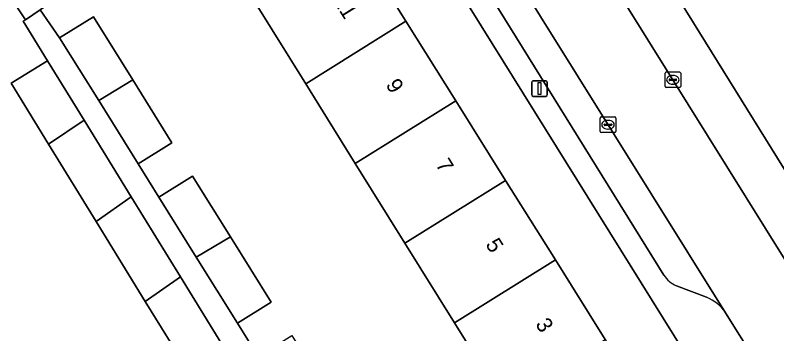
# Model space of a CAD drawing. Extents: x 160030 to 160839, y 385325 to 386450.
# Drawn here: x 160188.9 to 160237.55, y 386041.56 to 386061.92 of the extents above; entities that cross this region are included whole.
import ezdxf

# ---------------------------------------------------------------- set-up
doc = ezdxf.new("R2010")
doc.units = 0
for name, color, linetype in [('IMGEO_Erf', 7, 'Continuous'), ('IMGEO_Groenvoorziening', 7, 'Continuous'), ('IMGEO_Kolk', 7, 'Continuous'), ('IMGEO_Lichtmast', 7, 'Continuous'), ('IMGEO_Pand', 7, 'Continuous'), ('IMGEO_Pand_nummerreeks', 7, 'Continuous'), ('IMGEO_Parkeervlak_open', 7, 'Continuous'), ('IMGEO_Rijbaan_lokaal_open', 7, 'Continuous'), ('IMGEO_Voetpad_open', 7, 'Continuous')]:
    doc.layers.add(name, color=color, linetype=linetype)

msp = doc.modelspace()

# ---------------------------------------------------------------- linework, layer by layer
at = {"layer": 'IMGEO_Erf'}
for points in [[(160233.001, 386038.217), (160186.576, 386112.811)], [(160188.863, 386067.169), (160191.665, 386063.073), (160190.502, 386062.278), (160191.73, 386060.483), (160193.89, 386061.83), (160196.403, 386057.8), (160198.912, 386053.776), (160196.752, 386052.429), (160198.071, 386050.296), (160200.231, 386051.643), (160202.657, 386047.753), (160205.253, 386043.589), (160203.093, 386042.242), (160204.413, 386040.108), (160206.573, 386041.455), (160209.212, 386037.222), (160211.595, 386033.401), (160209.435, 386032.054), (160211.013, 386029.444), (160213.092, 386030.866), (160215.847, 386026.838), (160213.769, 386025.416), (160215.969, 386022.176), (160231.871, 386032.971)], [(160210.679, 386066.631), (160213.861, 386061.544), (160217.042, 386056.457), (160220.223, 386051.37), (160223.405, 386046.283), (160226.586, 386041.195), (160229.809, 386036.042), (160223.345, 386032.012), (160220.139, 386037.163), (160216.968, 386042.257), (160213.797, 386047.352), (160210.626, 386052.445), (160207.456, 386057.539), (160204.285, 386062.632)], [(160197.208, 386043.633), (160194.065, 386048.741), (160191.02, 386053.691), (160188.632, 386057.573), (160190.967, 386059.01), (160189.915, 386060.72), (160189.415, 386061.534), (160189.561, 386061.634), (160188.783, 386062.773)], [(160197.547, 386009.869), (160197.929, 386010.149), (160205.189, 386014.858), (160214.711, 386021.322), (160212.505, 386024.571), (160210.408, 386023.137), (160207.666, 386027.146), (160209.763, 386028.58), (160208.335, 386030.651), (160206.23, 386029.324), (160203.626, 386033.454), (160201.272, 386037.189), (160203.378, 386038.516), (160202.274, 386040.629), (160199.939, 386039.193), (160197.208, 386043.633)]]:
    msp.add_lwpolyline(points, dxfattribs=at)
at = {"layer": 'IMGEO_Groenvoorziening'}
msp.add_lwpolyline([(160212.738, 386092.855), (160243.449, 386043.345)], dxfattribs=at)
at = {"layer": 'IMGEO_Kolk'}
for p, q in [((160230.411, 386057.369), (160230.411, 386058.221)), ((160230.486, 386058.295), (160231.338, 386058.295)), ((160230.899, 386058.075), (160230.924, 386058.075)), ((160231.412, 386058.221), (160231.412, 386057.369)), ((160230.67, 386057.789), (160230.67, 386057.801)), ((160231.108, 386057.752), (160230.71, 386057.752)), ((160230.713, 386057.838), (160231.111, 386057.838)), ((160230.922, 386057.515), (160230.897, 386057.515)), ((160231.154, 386057.801), (160231.154, 386057.789)), ((160231.338, 386057.295), (160230.486, 386057.295)), ((160226.27, 386054.5), (160226.27, 386055.352)), ((160226.345, 386055.426), (160227.197, 386055.426)), ((160226.758, 386055.206), (160226.783, 386055.206)), ((160227.271, 386055.352), (160227.271, 386054.5)), ((160226.529, 386054.92), (160226.529, 386054.932)), ((160226.967, 386054.883), (160226.569, 386054.883)), ((160226.572, 386054.969), (160226.97, 386054.969)), ((160226.781, 386054.646), (160226.756, 386054.646)), ((160227.013, 386054.932), (160227.013, 386054.92)), ((160227.197, 386054.426), (160226.345, 386054.426))]:
    msp.add_line(p, q, dxfattribs=at)
for points in [[(160230.411, 386057.369), (160230.411, 386058.221)], [(160230.486, 386058.295), (160231.338, 386058.295)], [(160231.412, 386058.221), (160231.412, 386057.369)], [(160231.338, 386057.295), (160230.486, 386057.295)], [(160226.27, 386054.5), (160226.27, 386055.352)], [(160226.345, 386055.426), (160227.197, 386055.426)], [(160227.271, 386055.352), (160227.271, 386054.5)], [(160227.197, 386054.426), (160226.345, 386054.426)]]:
    msp.add_lwpolyline(points, dxfattribs=at)
for centre, radius, start, end in [((160230.488, 386058.219), 0.0765, 91.552, 178.448), ((160230.488, 386058.219), 0.0765, 91.552, 178.448), ((160231.336, 386058.219), 0.0765, 1.552, 88.448), ((160231.336, 386058.219), 0.0765, 1.552, 88.448), ((160230.71, 386057.798), 0.0403, 85.8775, 175.7526), ((160230.707, 386057.788), 0.0366, 178.938, 274.7102), ((160231.111, 386057.795), 0.043, 264.8664, 352.4533), ((160231.115, 386057.8), 0.0386, 1.7309, 96.639), ((160230.488, 386057.371), 0.0765, 181.552, 268.448), ((160230.488, 386057.371), 0.0765, 181.552, 268.448), ((160231.336, 386057.371), 0.0765, 271.552, 358.448), ((160231.336, 386057.371), 0.0765, 271.552, 358.448), ((160226.347, 386055.35), 0.0765, 91.552, 178.448), ((160226.347, 386055.35), 0.0765, 91.552, 178.448), ((160227.195, 386055.35), 0.0765, 1.552, 88.448), ((160227.195, 386055.35), 0.0765, 1.552, 88.448), ((160226.569, 386054.929), 0.0403, 85.8775, 175.7526), ((160226.566, 386054.919), 0.0366, 178.938, 274.7102), ((160226.97, 386054.926), 0.043, 264.8664, 352.4533), ((160226.974, 386054.931), 0.0386, 1.7309, 96.639), ((160226.347, 386054.502), 0.0765, 181.552, 268.448), ((160226.347, 386054.502), 0.0765, 181.552, 268.448), ((160227.195, 386054.502), 0.0765, 271.552, 358.448), ((160227.195, 386054.502), 0.0765, 271.552, 358.448)]:
    msp.add_arc(centre, radius, start, end, dxfattribs=at)
for centre, major_axis, ratio, start_param, end_param in [((160230.898, 386057.795), (-0.387, 0.002), 0.722429, 4.712389, 7.853982), ((160230.923, 386057.795), (-0.39, 0.002), 0.717154, 1.570796, 4.712389), ((160226.757, 386054.926), (-0.387, 0.002), 0.722429, 4.712389, 7.853982), ((160226.782, 386054.926), (-0.39, 0.002), 0.717154, 1.570796, 4.712389)]:
    msp.add_ellipse(centre, major_axis=major_axis, ratio=ratio, start_param=start_param, end_param=end_param, dxfattribs=at)
at = {"layer": 'IMGEO_Lichtmast'}
for p, q in [((160221.898, 386056.839), (160221.898, 386057.639)), ((160221.898, 386057.639), (160221.898, 386056.839)), ((160221.998, 386057.739), (160222.788, 386057.739)), ((160222.788, 386057.739), (160221.998, 386057.739)), ((160222.888, 386057.639), (160222.888, 386056.839)), ((160222.888, 386056.839), (160222.888, 386057.639)), ((160222.788, 386056.739), (160221.998, 386056.739)), ((160221.998, 386056.739), (160222.788, 386056.739))]:
    msp.add_line(p, q, dxfattribs=at)
msp.add_lwpolyline([(160222.318, 386057.614), (160222.468, 386057.614), (160222.468, 386056.864), (160222.318, 386056.864), (160222.318, 386057.614)], dxfattribs=at)
for centre, start, end in [((160221.998, 386057.639), 90, 180), ((160221.998, 386057.639), 90, 180), ((160222.788, 386057.639), 0, 90), ((160222.788, 386057.639), 360, 90), ((160221.998, 386056.839), 180, 270), ((160221.998, 386056.839), 180, 270), ((160222.788, 386056.839), 270, 0), ((160222.788, 386056.839), 270, 0)]:
    msp.add_arc(centre, 0.1, start, end, dxfattribs=at)
at = {"layer": 'IMGEO_Pand'}
for points in [[(160188.863, 386067.169), (160186.7, 386065.822), (160188.783, 386062.773), (160189.561, 386061.634), (160190.502, 386062.278), (160191.665, 386063.073)], [(160204.285, 386062.632), (160207.456, 386057.539), (160213.861, 386061.544), (160210.679, 386066.631)], [(160196.403, 386057.8), (160193.89, 386061.83), (160191.73, 386060.483), (160194.232, 386056.47)], [(160217.042, 386056.457), (160213.861, 386061.544), (160207.456, 386057.539), (160210.626, 386052.445)], [(160193.296, 386055.223), (160190.967, 386059.01), (160188.632, 386057.573), (160191.02, 386053.691)], [(160194.232, 386056.47), (160196.752, 386052.429), (160198.912, 386053.776), (160196.403, 386057.8)], [(160210.626, 386052.445), (160213.797, 386047.352), (160220.223, 386051.37), (160217.042, 386056.457)], [(160196.315, 386050.315), (160193.296, 386055.223), (160191.02, 386053.691), (160194.065, 386048.741)], [(160200.463, 386046.461), (160202.657, 386047.753), (160200.231, 386051.643), (160198.071, 386050.296)], [(160223.405, 386046.283), (160220.223, 386051.37), (160213.797, 386047.352), (160216.968, 386042.257)], [(160199.456, 386045.21), (160196.315, 386050.315), (160194.065, 386048.741), (160197.208, 386043.633)], [(160200.463, 386046.461), (160203.093, 386042.242), (160205.253, 386043.589), (160202.657, 386047.753)], [(160226.586, 386041.195), (160223.405, 386046.283), (160216.968, 386042.257), (160220.139, 386037.163)], [(160197.208, 386043.633), (160199.939, 386039.193), (160202.274, 386040.629), (160199.456, 386045.21)]]:
    msp.add_lwpolyline(points, close=True, dxfattribs=at)
at = {"layer": 'IMGEO_Parkeervlak_open'}
for points in [[(160234.281, 386042.907), (160198.933, 386099.578), (160191.24, 386111.976)], [(160191.916, 386107.243), (160230.344, 386045.305)], [(160231.148, 386044.637), (160233.057, 386043.894)]]:
    msp.add_lwpolyline(points, dxfattribs=at)
for centre, radius, start, end in [((160231.752, 386046.182), 1.658, 211.9098, 248.6475), ((160232.116, 386041.474), 2.596, 33.4913, 68.7452)]:
    msp.add_arc(centre, radius, start, end, dxfattribs=at)
at = {"layer": 'IMGEO_Rijbaan_lokaal_open'}
for points in [[(160189.926, 386114.094), (160191.24, 386111.976), (160198.933, 386099.578), (160234.281, 386042.907), (160236.171, 386039.885), (160236.489, 386039.496), (160245.768, 386024.457), (160247.407, 386021.819), (160258.344, 386004.227), (160260.98, 386000), (160265.703, 385991.996)], [(160262.33, 386007.837), (160254.635, 386019.699), (160249.611, 386027.802), (160240.779, 386041.933), (160240.647, 386042.176), (160219.316, 386076.396)]]:
    msp.add_lwpolyline(points, dxfattribs=at)
at = {"layer": 'IMGEO_Voetpad_open'}
for points in [[(160183.883, 386117.138), (160186.542, 386112.875), (160186.576, 386112.811), (160233.001, 386038.217), (160233.051, 386038.149), (160236.422, 386032.72)], [(160230.344, 386045.305), (160191.916, 386107.243)], [(160245.945, 386039.428), (160243.484, 386043.276), (160243.449, 386043.345), (160212.738, 386092.855)], [(160209.89, 386091.505), (160219.316, 386076.396), (160240.647, 386042.176)], [(160204.413, 386040.108), (160203.093, 386042.242), (160200.463, 386046.461), (160198.071, 386050.296), (160196.752, 386052.429), (160194.232, 386056.47), (160191.73, 386060.483), (160190.502, 386062.278), (160189.561, 386061.634), (160189.415, 386061.534), (160189.915, 386060.72), (160190.967, 386059.01), (160193.296, 386055.223), (160196.315, 386050.315), (160199.456, 386045.21), (160202.274, 386040.629)], [(160233.057, 386043.894), (160231.148, 386044.637)], [(160236.171, 386039.885), (160234.281, 386042.907)]]:
    msp.add_lwpolyline(points, dxfattribs=at)
for centre, radius, start, end in [((160231.752, 386046.182), 1.658, 211.9098, 248.6475), ((160232.116, 386041.474), 2.596, 33.4913, 68.7452)]:
    msp.add_arc(centre, radius, start, end, dxfattribs=at)

# ---------------------------------------------------------------- texts
at = {"layer": 'IMGEO_Pand_nummerreeks'}
for s, p in [('11', (160209.169, 386062.861)), ('9', (160212.539, 386057.472)), ('7', (160215.726, 386052.375)), ('5', (160218.914, 386047.278)), ('3', (160222.101, 386042.181))]:
    msp.add_text(s, height=1, rotation=302.0208, dxfattribs=at).set_placement(p)

doc.saveas('drawing.dxf')
